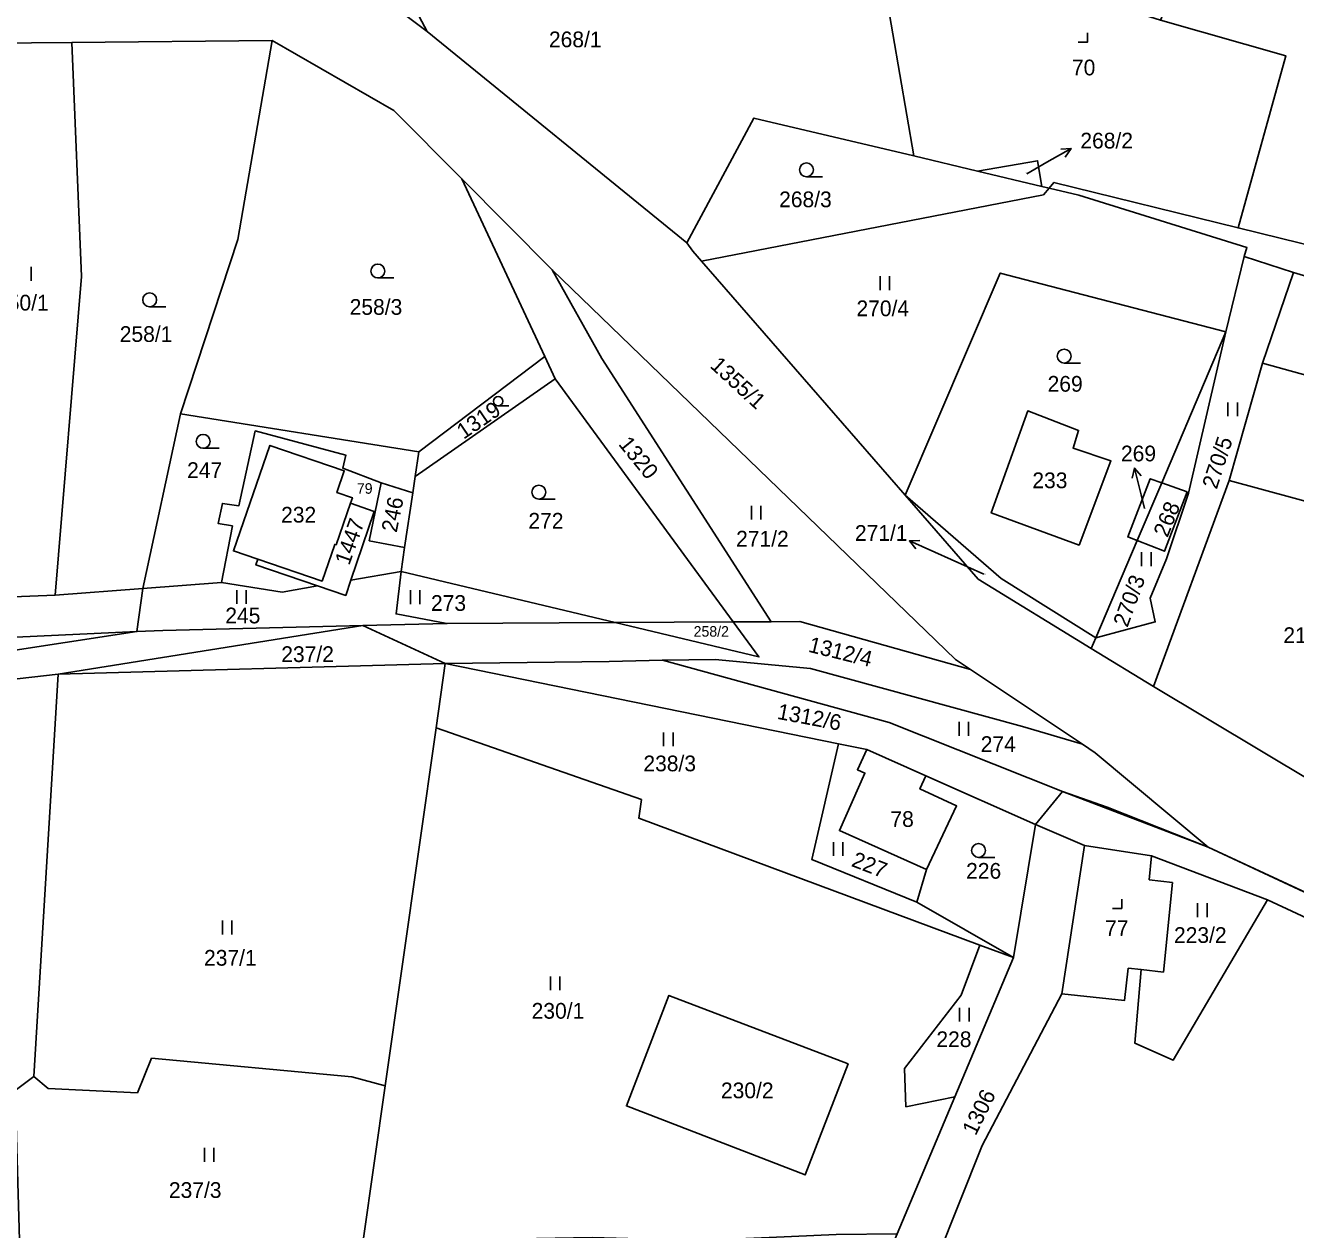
# Model space of a CAD drawing. Extents: x -588699 to -585793, y -1060280 to -1056731.
# Drawn here: x -587820.9 to -587683.7, y -1058227.3 to -1058097.1 of the extents above; entities that cross this region are included whole.
import ezdxf

# ---------------------------------------------------------------- set-up
doc = ezdxf.new("R2010")
doc.units = 0
for name, color, linetype in [('Druh pozemku', 7, 'Continuous'), ('Lesy', 7, 'Continuous'), ('Parcela nároku', 7, 'Continuous'), ('Parcelní číslo', 7, 'Continuous')]:
    doc.layers.add(name, color=color, linetype=linetype)

msp = doc.modelspace()

# ---------------------------------------------------------------- linework, layer by layer
at = {"layer": 'Druh pozemku'}
for p, q in [((-587734.78, -1058113.47), (-587736.53, -1058113.47)), ((-587820.33, -1058124.71), (-587820.33, -1058123.21)), ((-587781.11, -1058124.41), (-587782.86, -1058124.41)), ((-587728.56, -1058124.22), (-587728.56, -1058125.72)), ((-587727.54, -1058125.72), (-587727.54, -1058124.22)), ((-587805.77, -1058127.52), (-587807.52, -1058127.52)), ((-587706.92, -1058133.6), (-587708.67, -1058133.6)), ((-587768.68, -1058138.23), (-587769.85, -1058138.23)), ((-587690.98, -1058137.86), (-587690.98, -1058139.36)), ((-587689.95, -1058139.36), (-587689.95, -1058137.86)), ((-587799.99, -1058142.82), (-587801.74, -1058142.82)), ((-587763.7, -1058148.31), (-587765.45, -1058148.31)), ((-587742.48, -1058149.02), (-587742.48, -1058150.52)), ((-587741.45, -1058150.52), (-587741.45, -1058149.02)), ((-587700.3, -1058154.06), (-587700.3, -1058155.56)), ((-587699.28, -1058155.56), (-587699.28, -1058154.06)), ((-587798.09, -1058158.14), (-587798.09, -1058159.64)), ((-587797.07, -1058159.64), (-587797.07, -1058158.14)), ((-587779.33, -1058158.15), (-587779.33, -1058159.65)), ((-587778.31, -1058159.65), (-587778.31, -1058158.15)), ((-587720.03, -1058172.38), (-587720.03, -1058173.88)), ((-587719.01, -1058173.88), (-587719.01, -1058172.38)), ((-587751.98, -1058173.52), (-587751.98, -1058175.02)), ((-587750.95, -1058175.02), (-587750.95, -1058173.52)), ((-587733.61, -1058185.38), (-587733.61, -1058186.88)), ((-587732.58, -1058186.88), (-587732.58, -1058185.38)), ((-587716.17, -1058187.03), (-587717.92, -1058187.03)), ((-587694.25, -1058191.98), (-587694.25, -1058193.48)), ((-587693.22, -1058193.48), (-587693.22, -1058191.98)), ((-587799.66, -1058193.86), (-587799.66, -1058195.36)), ((-587798.64, -1058195.36), (-587798.64, -1058193.86)), ((-587764.19, -1058199.9), (-587764.19, -1058201.4)), ((-587763.17, -1058201.4), (-587763.17, -1058199.9)), ((-587719.98, -1058203.29), (-587719.98, -1058204.79)), ((-587718.95, -1058204.79), (-587718.95, -1058203.29)), ((-587801.6, -1058218.43), (-587801.6, -1058219.93)), ((-587800.58, -1058219.93), (-587800.58, -1058218.43))]:
    msp.add_line(p, q, dxfattribs=at)
for points in [[(-587707.14, -1058098.91), (-587706.14, -1058098.91), (-587706.14, -1058097.91)], [(-587703.44, -1058192.55), (-587702.44, -1058192.55), (-587702.44, -1058191.55)]]:
    msp.add_lwpolyline(points, dxfattribs=at)
for centre, radius in [((-587736.53, -1058112.72), 0.75), ((-587782.86, -1058123.66), 0.75), ((-587807.52, -1058126.77), 0.75), ((-587708.67, -1058132.85), 0.75), ((-587769.85, -1058137.73), 0.503), ((-587801.74, -1058142.07), 0.75), ((-587765.45, -1058147.56), 0.75), ((-587717.92, -1058186.28), 0.75)]:
    msp.add_circle(centre, radius, dxfattribs=at)
at = {"layer": 'Lesy'}
for p, q in [((-587790.12, -1058088.31), (-587777.51, -1058097.76)), ((-587777.51, -1058097.76), (-587749.47, -1058120.61)), ((-587749.47, -1058120.61), (-587742.2, -1058107.12)), ((-587742.2, -1058107.12), (-587742.2, -1058107.12)), ((-587742.2, -1058107.12), (-587724.91, -1058111.22)), ((-587724.91, -1058111.22), (-587718.02, -1058112.86)), ((-587718.02, -1058112.86), (-587711.07, -1058114.51)), ((-587711.07, -1058114.51), (-587710.29, -1058114.69)), ((-587710.29, -1058114.69), (-587707.09, -1058115.45)), ((-587707.09, -1058115.45), (-587688.91, -1058121.13)), ((-587688.91, -1058121.13), (-587689.21, -1058122.09)), ((-587689.21, -1058122.09), (-587683.87, -1058123.82)), ((-587683.87, -1058123.82), (-587662.16, -1058130.38)), ((-587708.86, -1058179.93), (-587711.77, -1058183.47)), ((-587693.12, -1058185.92), (-587708.86, -1058179.93)), ((-587711.77, -1058183.47), (-587714.16, -1058197.87)), ((-587672.96, -1058195.32), (-587693.12, -1058185.92)), ((-587714.16, -1058197.87), (-587720.49, -1058212.9)), ((-587720.49, -1058212.9), (-587726.73, -1058227.72))]:
    msp.add_line(p, q, dxfattribs=at)
at = {"layer": 'Parcela nároku'}
for points in [[(-587666.34, -1058066.98), (-587690.45, -1058069.72), (-587696.04, -1058088.13), (-587696.51, -1058092.47), (-587698.26, -1058096.54), (-587684.71, -1058100.39), (-587689.87, -1058118.99), (-587660.3, -1058126.28), (-587654.29, -1058089.61), (-587651.15, -1058061.4)], [(-587754.2, -1058075.69), (-587776.14, -1058082.82), (-587784.18, -1058085.22), (-587777.51, -1058097.76), (-587749.47, -1058120.61), (-587742.2, -1058107.12), (-587724.91, -1058111.22), (-587727.96, -1058093.59), (-587736.75, -1058095.11), (-587737.67, -1058087.54), (-587745.35, -1058088.61), (-587747.05, -1058074.89)], [(-587698.26, -1058096.54), (-587702.97, -1058095.06), (-587703.14, -1058087.19), (-587717.57, -1058087.57), (-587717.48, -1058091.77), (-587723.72, -1058092.85), (-587727.96, -1058093.59), (-587724.91, -1058111.22), (-587718.02, -1058112.86), (-587711.55, -1058111.74), (-587711.07, -1058114.51), (-587710.29, -1058114.69), (-587709.77, -1058114.08), (-587689.87, -1058118.99), (-587684.71, -1058100.39)], [(-587850.57, -1058105.64), (-587829.03, -1058099.08), (-587815.92, -1058098.95), (-587814.88, -1058124.25), (-587817.73, -1058158.68), (-587829.62, -1058159.17), (-587827.97, -1058122.42), (-587851.39, -1058121.17)], [(-587817.73, -1058158.68), (-587814.88, -1058124.25), (-587815.92, -1058098.95), (-587794.26, -1058098.73), (-587797.98, -1058120.24), (-587804.17, -1058139.08), (-587808.26, -1058157.99)], [(-587794.26, -1058098.73), (-587781.14, -1058106.31), (-587773.78, -1058113.71), (-587764.8, -1058132.9), (-587778.41, -1058143.21), (-587804.17, -1058139.08), (-587797.98, -1058120.24)], [(-587710.29, -1058114.69), (-587711.07, -1058114.51), (-587718.02, -1058112.86), (-587724.91, -1058111.22), (-587742.2, -1058107.12), (-587749.47, -1058120.61), (-587748.81, -1058121.5), (-587747.87, -1058122.58), (-587710.91, -1058115.41)], [(-587711.55, -1058111.74), (-587711.07, -1058114.51), (-587718.02, -1058112.86)], [(-587773.78, -1058113.71), (-587764.02, -1058123.53), (-587758.63, -1058133.13), (-587740.33, -1058161.56), (-587744.45, -1058161.58), (-587763.67, -1058135.32), (-587764.8, -1058132.9)], [(-587707.09, -1058115.45), (-587688.91, -1058121.13), (-587689.21, -1058122.09), (-587691.19, -1058130.24), (-587715.58, -1058123.88), (-587725.85, -1058147.88), (-587747.87, -1058122.58), (-587710.91, -1058115.41), (-587710.29, -1058114.69)], [(-587689.87, -1058118.99), (-587709.77, -1058114.08), (-587710.29, -1058114.69), (-587707.09, -1058115.45), (-587688.91, -1058121.13), (-587689.21, -1058122.09), (-587683.87, -1058123.82), (-587662.16, -1058130.38), (-587658.78, -1058130.54), (-587657.5, -1058126.98), (-587660.3, -1058126.28)], [(-587705.24, -1058163.3), (-587698.82, -1058161.58), (-587699.38, -1058159.03), (-587697.61, -1058154.77), (-587695.23, -1058147.68), (-587691.19, -1058130.24), (-587689.21, -1058122.09), (-587683.87, -1058123.82), (-587687.23, -1058133.62), (-587690.83, -1058146.29), (-587699.03, -1058168.58), (-587705.74, -1058164.47)], [(-587720.43, -1058165.64), (-587764.02, -1058123.53), (-587758.63, -1058133.13), (-587740.33, -1058161.56), (-587737.23, -1058161.54), (-587718.79, -1058166.72)], [(-587691.19, -1058130.24), (-587715.58, -1058123.88), (-587725.85, -1058147.88), (-587715.49, -1058156.9), (-587705.24, -1058163.3), (-587700.78, -1058152.8), (-587701.79, -1058152.4), (-587699.37, -1058146.11), (-587698.12, -1058146.56)], [(-587687.23, -1058133.62), (-587683.87, -1058123.82), (-587662.16, -1058130.38), (-587664.46, -1058139.91)], [(-587697.82, -1058153.95), (-587700.78, -1058152.8), (-587705.24, -1058163.3), (-587698.82, -1058161.58), (-587699.38, -1058159.03), (-587697.61, -1058154.77), (-587695.23, -1058147.68), (-587691.19, -1058130.24), (-587698.12, -1058146.56), (-587695.39, -1058147.53)], [(-587778.81, -1058145.87), (-587778.41, -1058143.21), (-587764.8, -1058132.9), (-587763.67, -1058135.32)], [(-587664.46, -1058139.91), (-587687.23, -1058133.62), (-587690.83, -1058146.29), (-587676.77, -1058150.1), (-587676.18, -1058147.49), (-587675.41, -1058144.07), (-587665.56, -1058144.03)], [(-587763.67, -1058135.32), (-587778.81, -1058145.87), (-587779.08, -1058147.64), (-587779.96, -1058153.54), (-587780.34, -1058156.12), (-587757.2, -1058161.65), (-587744.45, -1058161.58)], [(-587786.3, -1058143.57), (-587786.63, -1058144.97), (-587782.49, -1058146.55), (-587779.08, -1058147.64), (-587778.81, -1058145.87), (-587778.41, -1058143.21), (-587804.17, -1058139.08), (-587808.26, -1058157.99), (-587799.76, -1058157.34), (-587798.58, -1058151.2), (-587800.11, -1058150.95), (-587799.66, -1058148.77), (-587797.87, -1058149.03), (-587796.11, -1058140.94)], [(-587703.62, -1058144.16), (-587707.71, -1058142.8), (-587707.12, -1058140.89), (-587712.6, -1058138.77), (-587716.56, -1058149.81), (-587707.05, -1058153.28)], [(-587707.05, -1058153.28), (-587703.62, -1058144.16), (-587707.71, -1058142.8), (-587707.12, -1058140.89), (-587712.6, -1058138.77), (-587716.56, -1058149.81)], [(-587797.87, -1058149.03), (-587796.11, -1058140.94), (-587786.3, -1058143.57), (-587786.63, -1058144.97), (-587782.49, -1058146.55), (-587783.78, -1058152.81), (-587779.96, -1058153.54), (-587780.34, -1058156.12), (-587785.77, -1058157.07), (-587783.24, -1058149.64), (-587785.81, -1058148.75), (-587785.61, -1058148.17), (-587787.28, -1058147.6), (-587786.48, -1058145.27), (-587794.51, -1058142.51), (-587798.47, -1058153.91), (-587795.82, -1058154.81), (-587796.03, -1058155.43), (-587789.36, -1058157.69), (-587793.2, -1058158.36), (-587799.76, -1058157.34), (-587798.58, -1058151.2), (-587800.11, -1058150.95), (-587799.66, -1058148.77)], [(-587785.61, -1058148.17), (-587787.28, -1058147.6), (-587786.48, -1058145.27), (-587794.51, -1058142.51), (-587798.47, -1058153.91), (-587795.82, -1058154.81), (-587788.88, -1058157.17), (-587787.51, -1058153.2), (-587787.37, -1058153.25), (-587785.81, -1058148.75)], [(-587676.77, -1058150.1), (-587676.18, -1058147.49), (-587675.41, -1058144.07), (-587665.56, -1058144.03), (-587667.1, -1058149.78), (-587668.76, -1058155.99), (-587675.83, -1058182.43), (-587699.03, -1058168.58), (-587690.83, -1058146.29)], [(-587699.37, -1058146.11), (-587698.12, -1058146.56), (-587700.78, -1058152.8), (-587701.79, -1058152.4)], [(-587782.49, -1058146.55), (-587779.08, -1058147.64), (-587779.96, -1058153.54), (-587783.78, -1058152.81)], [(-587698.12, -1058146.56), (-587695.39, -1058147.53), (-587697.82, -1058153.95), (-587700.78, -1058152.8)], [(-587787.51, -1058153.2), (-587787.37, -1058153.25), (-587785.81, -1058148.75), (-587783.24, -1058149.64), (-587785.77, -1058157.07), (-587786.33, -1058158.72), (-587789.36, -1058157.69), (-587796.03, -1058155.43), (-587795.82, -1058154.81), (-587788.88, -1058157.17)], [(-587715.49, -1058156.9), (-587725.85, -1058147.88), (-587717.98, -1058156.96), (-587705.74, -1058164.47), (-587705.24, -1058163.3)], [(-587808.26, -1058157.99), (-587817.73, -1058158.68), (-587829.62, -1058159.17), (-587829.72, -1058161.43), (-587849.78, -1058161.08), (-587869.67, -1058159.74), (-587869.72, -1058158.8), (-587886.03, -1058156.97), (-587902.06, -1058159.35), (-587901.92, -1058163.88), (-587888.85, -1058160.69), (-587848.18, -1058164.46), (-587808.9, -1058162.63)], [(-587808.26, -1058157.99), (-587808.9, -1058162.63), (-587806.11, -1058162.5), (-587784.46, -1058161.98), (-587775.38, -1058161.76), (-587780.89, -1058160.72), (-587780.34, -1058156.12), (-587785.77, -1058157.07), (-587786.33, -1058158.72), (-587789.36, -1058157.69), (-587793.2, -1058158.36), (-587799.76, -1058157.34)], [(-587780.34, -1058156.12), (-587757.2, -1058161.65), (-587775.38, -1058161.76), (-587780.89, -1058160.72)], [(-587888.85, -1058160.69), (-587901.92, -1058163.88), (-587888.68, -1058161.9), (-587852.03, -1058167.69), (-587840.39, -1058167.44), (-587808.9, -1058162.63), (-587848.18, -1058164.46)], [(-587741.67, -1058165.37), (-587757.2, -1058161.65), (-587775.38, -1058161.76), (-587784.46, -1058161.98), (-587775.59, -1058166.09), (-587757.86, -1058165.85), (-587752.09, -1058165.71), (-587746.39, -1058165.63), (-587736.1, -1058166.62), (-587713.17, -1058172.89), (-587706.68, -1058174.81), (-587718.79, -1058166.72), (-587737.23, -1058161.54), (-587740.33, -1058161.56), (-587744.45, -1058161.58)], [(-587757.2, -1058161.65), (-587744.45, -1058161.58), (-587741.67, -1058165.37)], [(-587817.41, -1058167.23), (-587784.46, -1058161.98), (-587775.59, -1058166.09)], [(-587727.58, -1058172.44), (-587752.09, -1058165.71), (-587757.86, -1058165.85), (-587775.59, -1058166.09), (-587733.07, -1058174.75), (-587730.01, -1058175.37), (-587723.61, -1058178.22), (-587711.77, -1058183.47), (-587708.86, -1058179.93)], [(-587693.12, -1058185.92), (-587705.33, -1058175.73), (-587706.68, -1058174.81), (-587713.17, -1058172.89), (-587736.1, -1058166.62), (-587746.39, -1058165.63), (-587752.09, -1058165.71), (-587727.58, -1058172.44), (-587708.86, -1058179.93), (-587704.04, -1058181.62)], [(-587817.41, -1058167.23), (-587775.59, -1058166.09), (-587776.54, -1058173.02), (-587782.05, -1058211.71), (-587785.66, -1058210.74), (-587807.31, -1058208.75), (-587808.84, -1058212.5), (-587818.5, -1058212.03), (-587820.04, -1058210.7)], [(-587775.59, -1058166.09), (-587776.54, -1058173.02), (-587754.36, -1058180.78), (-587754.65, -1058182.79), (-587717.78, -1058196.52), (-587714.16, -1058197.87), (-587724.6, -1058191.89), (-587735.95, -1058187.25), (-587733.07, -1058174.75)], [(-587834.19, -1058169.13), (-587842.96, -1058169.39), (-587845.87, -1058217.7), (-587826.15, -1058215.31), (-587822.07, -1058212.23), (-587820.04, -1058210.7), (-587817.41, -1058167.23)], [(-587725.77, -1058213.98), (-587725.94, -1058209.85), (-587719.82, -1058201.93), (-587717.78, -1058196.52), (-587754.65, -1058182.79), (-587754.36, -1058180.78), (-587776.54, -1058173.02), (-587782.05, -1058211.71), (-587784.43, -1058228.44), (-587765.7, -1058228.21), (-587759.68, -1058228.13), (-587748.07, -1058228.46), (-587740.57, -1058228.12), (-587733.31, -1058227.8), (-587726.73, -1058227.72), (-587720.49, -1058212.9)], [(-587731.01, -1058177.56), (-587730.2, -1058177.93), (-587732.97, -1058184.13), (-587723.56, -1058188.34), (-587724.6, -1058191.89), (-587735.95, -1058187.25), (-587733.07, -1058174.75), (-587730.01, -1058175.37)], [(-587723.61, -1058178.22), (-587730.01, -1058175.37), (-587731.01, -1058177.56), (-587730.2, -1058177.93), (-587732.97, -1058184.13), (-587723.56, -1058188.34), (-587720.29, -1058181.48), (-587724.27, -1058179.63)], [(-587723.61, -1058178.22), (-587724.27, -1058179.63), (-587720.29, -1058181.48), (-587723.56, -1058188.34), (-587724.6, -1058191.89), (-587714.16, -1058197.87), (-587711.77, -1058183.47)], [(-587641.1, -1058215.41), (-587623.22, -1058232.65), (-587626.75, -1058230.81), (-587631.42, -1058228.44), (-587642.62, -1058218.23), (-587676.1, -1058196.56), (-587686.68, -1058191.64), (-587699.23, -1058186.88), (-587706.46, -1058185.75), (-587711.77, -1058183.47), (-587708.86, -1058179.93), (-587704.04, -1058181.62), (-587693.12, -1058185.92), (-587672.96, -1058195.32), (-587652.53, -1058206.85)], [(-587726.73, -1058227.72), (-587732.95, -1058242.49), (-587729.82, -1058248.97), (-587717.53, -1058218.16), (-587708.93, -1058201.78), (-587706.46, -1058185.75), (-587711.77, -1058183.47), (-587714.16, -1058197.87), (-587720.49, -1058212.9)], [(-587699.48, -1058189.46), (-587696.97, -1058189.75), (-587697.95, -1058199.44), (-587700.35, -1058199.17), (-587701.75, -1058199.02), (-587702.14, -1058202.49), (-587708.93, -1058201.78), (-587706.46, -1058185.75), (-587699.23, -1058186.88)], [(-587696.97, -1058189.75), (-587697.95, -1058199.44), (-587700.35, -1058199.17), (-587701.04, -1058207.1), (-587696.89, -1058208.97), (-587686.68, -1058191.64), (-587699.23, -1058186.88), (-587699.48, -1058189.46)], [(-587700.35, -1058199.17), (-587701.75, -1058199.02), (-587702.14, -1058202.49), (-587708.93, -1058201.78), (-587717.53, -1058218.16), (-587729.82, -1058248.97), (-587719.99, -1058253.31), (-587674.16, -1058288.28), (-587646.41, -1058281.16), (-587640.42, -1058275.85), (-587635.5, -1058262.73), (-587628.39, -1058236.86), (-587631.42, -1058228.44), (-587642.62, -1058218.23), (-587676.1, -1058196.56), (-587686.68, -1058191.64), (-587696.89, -1058208.97), (-587701.04, -1058207.1)], [(-587717.78, -1058196.52), (-587714.16, -1058197.87), (-587720.49, -1058212.9), (-587725.77, -1058213.98), (-587725.94, -1058209.85), (-587719.82, -1058201.93)], [(-587736.65, -1058221.36), (-587755.98, -1058213.9), (-587751.4, -1058201.95), (-587732.02, -1058209.35)], [(-587755.98, -1058213.9), (-587751.4, -1058201.95), (-587732.02, -1058209.35), (-587736.65, -1058221.36)], [(-587782.05, -1058211.71), (-587785.66, -1058210.74), (-587807.31, -1058208.75), (-587808.84, -1058212.5), (-587818.5, -1058212.03), (-587820.04, -1058210.7), (-587822.07, -1058212.23), (-587821.15, -1058243.34), (-587818.31, -1058243.66), (-587818.31, -1058231.95), (-587809.37, -1058232.33), (-587801.84, -1058231.28), (-587784.43, -1058228.44)]]:
    msp.add_lwpolyline(points, close=True, dxfattribs=at)
for points in [[(-587784.18, -1058085.22), (-587777.51, -1058097.76), (-587790.12, -1058088.31)], [(-587790.12, -1058088.31), (-587777.51, -1058097.76), (-587749.47, -1058120.61), (-587748.81, -1058121.5), (-587747.87, -1058122.58), (-587725.85, -1058147.88), (-587717.98, -1058156.96), (-587705.74, -1058164.47), (-587699.03, -1058168.58), (-587675.83, -1058182.43), (-587673.63, -1058183.75), (-587651.25, -1058196.73), (-587647.29, -1058199.37), (-587635.6, -1058208.26), (-587618.05, -1058223.79), (-587609.63, -1058229.16), (-587606.63, -1058230.47), (-587596.04, -1058235.08), (-587594.11, -1058230.47), (-587543.81, -1058245.62)], [(-587546.41, -1058255.87), (-587580.84, -1058246.64), (-587593.55, -1058244.64), (-587613.43, -1058237.77), (-587623.22, -1058232.65), (-587641.1, -1058215.41), (-587652.53, -1058206.85), (-587672.96, -1058195.32), (-587693.12, -1058185.92), (-587705.33, -1058175.73), (-587706.68, -1058174.81), (-587718.79, -1058166.72), (-587720.43, -1058165.64), (-587764.02, -1058123.53), (-587773.78, -1058113.71), (-587781.14, -1058106.31), (-587794.26, -1058098.73), (-587815.92, -1058098.95), (-587829.03, -1058099.08)], [(-587834.19, -1058169.13), (-587817.41, -1058167.23), (-587784.46, -1058161.98), (-587806.11, -1058162.5), (-587808.9, -1058162.63), (-587840.39, -1058167.44)]]:
    msp.add_lwpolyline(points, dxfattribs=at)
at = {"layer": 'Parcelní číslo'}
for p, q in [((-587710.53, -1058111.9), (-587707.92, -1058110.41)), ((-587712.7, -1058113.14), (-587710.53, -1058111.9)), ((-587700.36, -1058147.86), (-587701.08, -1058144.95)), ((-587699.99, -1058149.33), (-587700.36, -1058147.86)), ((-587722.66, -1058154.05), (-587725.4, -1058152.82)), ((-587717.36, -1058156.43), (-587722.66, -1058154.05))]:
    msp.add_line(p, q, dxfattribs=at)
for points in [[(-587709.04, -1058110.47), (-587707.92, -1058110.41), (-587708.55, -1058111.34)], [(-587701.33, -1058146.04), (-587701.08, -1058144.95), (-587700.36, -1058145.8)], [(-587724.69, -1058153.69), (-587725.4, -1058152.82), (-587724.28, -1058152.77)]]:
    msp.add_lwpolyline(points, dxfattribs=at)

# ---------------------------------------------------------------- texts
at = {"layer": 'Parcela nároku'}
for s, height, p in [('268/1', 1.7, (-587764.36, -1058099.47)), ('70', 1.7, (-587707.83, -1058102.51)), ('268/2', 0.1, (-587712.89, -1058113.14)), ('268/3', 1.7, (-587739.48, -1058116.76)), ('250/1', 1.7, (-587824.12, -1058127.93)), ('258/3', 1.7, (-587785.9, -1058128.39)), ('270/4', 1.7, (-587731.12, -1058128.54)), ('258/1', 1.7, (-587810.75, -1058131.32)), ('269', 1.7, (-587710.46, -1058136.7)), ('247', 1.7, (-587803.47, -1058146.03)), ('233', 1.7, (-587712.11, -1058147.13)), ('79', 1.14, (-587785.12, -1058147.73)), ('232', 1.7, (-587793.31, -1058150.85)), ('269', 0.1, (-587700.1, -1058149.33)), ('272', 1.7, (-587766.58, -1058151.5)), ('271/2', 1.7, (-587744.13, -1058153.44)), ('271/1', 0.1, (-587717.5, -1058156.43)), ('273', 1.7, (-587777.11, -1058160.39)), ('245', 1.7, (-587799.34, -1058161.74)), ('258/2', 1.14, (-587748.72, -1058163.18)), ('215', 1.7, (-587684.98, -1058163.87)), ('237/2', 1.7, (-587793.29, -1058165.92)), ('274', 1.7, (-587717.69, -1058175.64)), ('238/3', 1.7, (-587754.15, -1058177.73)), ('78', 1.7, (-587727.45, -1058183.74)), ('226', 1.7, (-587719.27, -1058189.34)), ('77', 1.7, (-587704.25, -1058195.54)), ('223/2', 1.7, (-587696.8, -1058196.28)), ('237/1', 1.7, (-587801.64, -1058198.74)), ('230/1', 1.7, (-587766.23, -1058204.47)), ('228', 1.7, (-587722.48, -1058207.54)), ('230/2', 1.7, (-587745.77, -1058213.07)), ('237/3', 1.7, (-587805.44, -1058223.84))]:
    msp.add_text(s, height=height, dxfattribs=at).set_placement(p)
for s, rotation, p in [('1355/1', 317.4604, (-587747.04, -1058134.01)), ('1319', 34.3628, (-587773.58, -1058141.9)), ('1320', 309.183, (-587756.92, -1058142.4)), ('270/5', 72.1332, (-587692.18, -1058147.32)), ('246', 78.4284, (-587780.82, -1058151.99)), ('268', 68.2988, (-587697.5, -1058152.54)), ('1447', 70.4126, (-587785.95, -1058155.55)), ('270/3', 69.8949, (-587701.83, -1058162.25)), ('1312/4', 346.1501, (-587736.41, -1058164.8)), ('1312/6', 349.2473, (-587739.77, -1058172.05)), ('227', 338.9097, (-587731.77, -1058187.95)), ('1306', 63.9041, (-587718.24, -1058217.2))]:
    msp.add_text(s, height=1.7, rotation=rotation, dxfattribs=at).set_placement(p)
at = {"layer": 'Parcelní číslo'}
for s, p in [('268/2', (-587706.92, -1058110.41)), ('269', (-587702.53, -1058144.23)), ('271/1', (-587731.29, -1058152.82))]:
    msp.add_text(s, height=1.7, dxfattribs=at).set_placement(p)

doc.saveas('drawing.dxf')
